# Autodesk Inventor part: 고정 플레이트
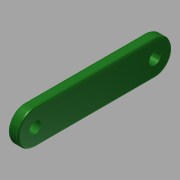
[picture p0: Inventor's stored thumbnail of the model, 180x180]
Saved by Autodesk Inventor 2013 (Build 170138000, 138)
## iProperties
Created: 2017-04
Part Number: 고정 플레이트
Material: 스테인리스강
Document SubType Name: Modeling
Designer: mduedu
Density: 8.08 g/cm^3
Mass: 9.86034 g
Surface Area: 11.4535 cm^2
Volume: 1.22034 cm^3
Author: mduedu
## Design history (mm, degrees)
sketch "스케치1"
  geometry: L1 (0, 17.5)-(0, -17.5); L2 (-5, 17.5)-(-5, -17.5); L3 (5, -17.5)-(5, 17.5); A1 r 5 centre (0, 17.5) between (5, 17.5) and (-5, 17.5); A2 r 5 centre (0, -17.5) between (-5, -17.5) and (5, -17.5); 2 further points
  constraints: 6 end point, 4 point on circle, 4 tangent, 3 coincident, 2 centre point, 1 midpoint, 1 parallel, 1 vertical
  dimensions: "d0" = 35 distance of L1.start L1.end; "d1" = 5 radius of A2
extrude "돌출1" new body sketch "스케치1" distance "d2" = 3; taper "d3" = 0 deg
fillet "모깎기1" dims "d4" = 0.5
sketch "스케치2"
  geometry: A1 r 5 centre (-17.5, 0) between (-17.5, 5) and (-17.5, -5) reference; A2 r 5 centre (17.5, 0) between (17.5, -5) and (17.5, 5) reference; 3 further points
  constraints: 2 coincident
sketch "스케치3"
  geometry: 3 further points
  constraints: 3 other
hole "구멍1" sketch "스케치3" at (-17.5, 0), (17.5, 0) diameter "d5" = 3.4; stored, may be unused: countersink angle "d9" = 90 deg, drill point angle "d11" = 0 deg; dims "d6" = 6, "d7" = 4, "d8" = 2, "d10" = 8
node "솔리드1"
